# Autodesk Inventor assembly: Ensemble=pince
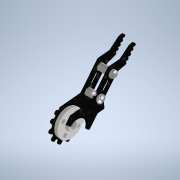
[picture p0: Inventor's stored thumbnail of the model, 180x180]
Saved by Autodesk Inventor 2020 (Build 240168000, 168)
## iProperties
Created: 2021-10
Part Number: Ensemble=pince
Document SubType Name: Assembly
Designer: bruno
Author: bruno
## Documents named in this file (5)
- C:\Users\bruno\OneDrive\Bureau\Robot-Inventor\Robot-equillibrage\Ensemble-pince.iam
- C:\Users\bruno\OneDrive\Bureau\Robot-Inventor\Robot-equillibrage\Ensemble-doigt.iam
- C:\Users\bruno\OneDrive\Bureau\Robot-Inventor\Robot-equillibrage\pince-2.ipt
- C:\Users\bruno\OneDrive\Bureau\Robot-Inventor\Robot-equillibrage\embout-servo.ipt
- C:\Users\bruno\Documents\Inventor\Content Center Files\R2020\fr-FR\ANSI B18.6.7M(01)\ANSI B18.6.7M - M3x0,5 x 5(5).ipt
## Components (6 placed, 4 different names)
1. Ensemble-doigt:1 [sub-assembly] — Placage:1, Placage:2, Placage:8, Logement:3
2. pince-2:1 — Logement:3, Logement:4, Logement:5
3. embout-servo:1 — Placage:1, Placage:2, Placage:7
4. Vis à tête tronconique à empreinte cruciforme - Type IA - Métrique M3x0,5 x 5:1 — Logement:4
5. Vis à tête tronconique à empreinte cruciforme - Type IA - Métrique M3x0,5 x 5:2 — Logement:5
6. Vis à tête tronconique à empreinte cruciforme - Type IA - Métrique M3x0,5 x 5:3 — Placage:7, Placage:8
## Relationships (7: Mate 4, Insert 3)
- Placage:1 [Mate]: Ensemble-doigt:1 ↔ embout-servo:1
- Placage:2 [Mate]: Ensemble-doigt:1 ↔ embout-servo:1
- Placage:7 [Mate]: embout-servo:1 ↔ Vis à tête tronconique à empreinte cruciforme - Type IA - Métrique M3x0,5 x 5:3
- Placage:8 [Mate]: Ensemble-doigt:1 ↔ Vis à tête tronconique à empreinte cruciforme - Type IA - Métrique M3x0,5 x 5:3
- Logement:3 [Insert]: Ensemble-doigt:1 ↔ pince-2:1
- Logement:4 [Insert]: pince-2:1 ↔ Vis à tête tronconique à empreinte cruciforme - Type IA - Métrique M3x0,5 x 5:1
- Logement:5 [Insert]: pince-2:1 ↔ Vis à tête tronconique à empreinte cruciforme - Type IA - Métrique M3x0,5 x 5:2
